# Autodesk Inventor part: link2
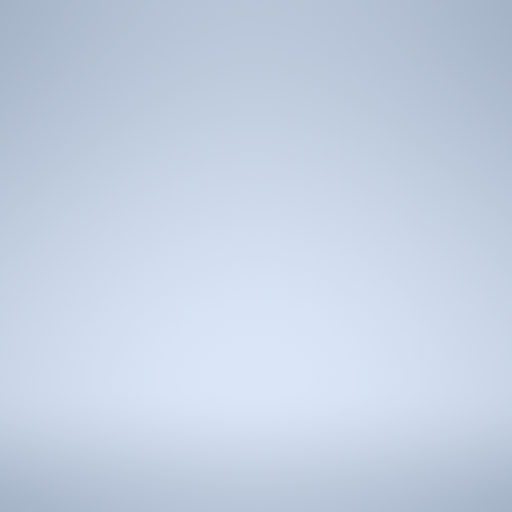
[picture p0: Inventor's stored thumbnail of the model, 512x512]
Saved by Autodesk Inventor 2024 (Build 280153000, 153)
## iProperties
Created: 2023-10
Part Number: link2
Material: Generic
Document SubType Name: Modeling
Designer: ESTUDIANTE
Density: 1 g/cm^3
Appearance: Default
Author: ESTUDIANTE
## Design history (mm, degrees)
